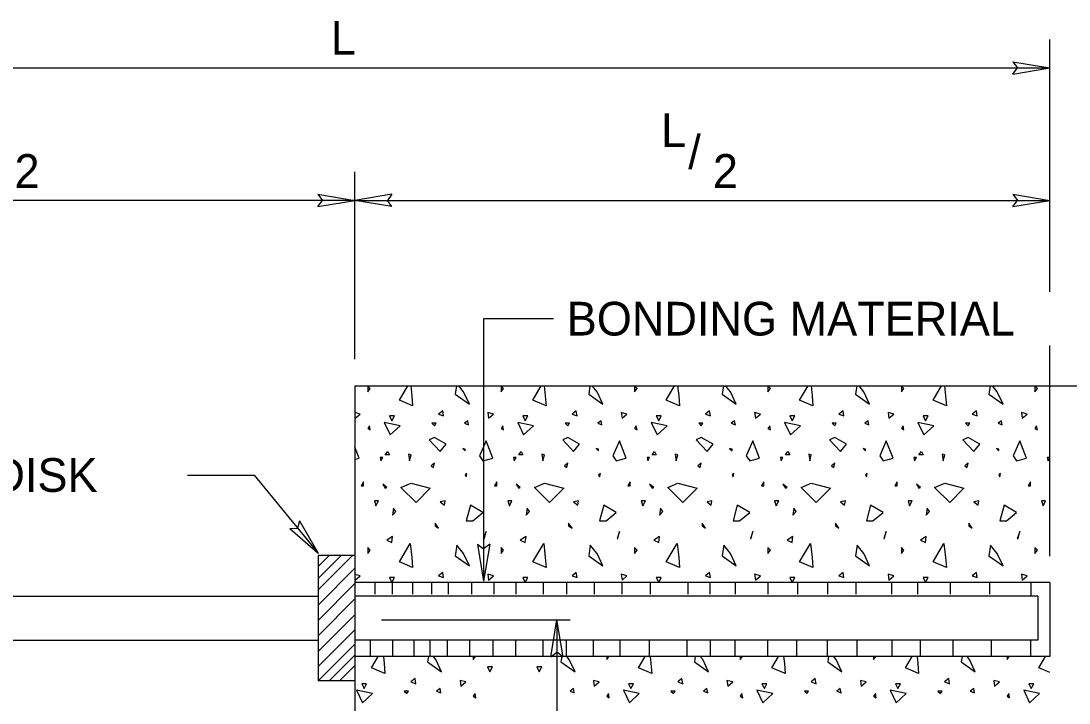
# Model space of a CAD drawing. Extents: x 2.92 to 10.05, y 1.3 to 10.63.
# Drawn here: x 5.007 to 6.873, y 6.811 to 8.026 of the extents above; entities that cross this region are included whole.
import ezdxf

# ---------------------------------------------------------------- set-up
doc = ezdxf.new("R2010")
doc.units = 0
for name, color, linetype in [('DETL-DIMS', 7, 'Continuous'), ('DETL-LINE', 7, 'Continuous'), ('DETL-NOTE', 7, 'Continuous'), ('DETL-PATT', 7, 'Continuous')]:
    doc.layers.add(name, color=color, linetype=linetype)

msp = doc.modelspace()

# ---------------------------------------------------------------- linework, layer by layer
at = {"layer": 'DETL-DIMS'}
for p, q in [((6.8384, 7.5436), (6.8384, 7.9925)), ((6.7725, 7.953), (6.8384, 7.942)), ((6.7725, 7.953), (6.7808, 7.942)), ((4.3073, 7.942), (6.8384, 7.942)), ((6.7725, 7.9311), (6.8384, 7.942)), ((6.7725, 7.9311), (6.7808, 7.942)), ((5.6014, 7.4233), (5.6014, 7.7572)), ((5.5355, 7.717), (5.6014, 7.706)), ((5.5355, 7.717), (5.5438, 7.706)), ((5.6673, 7.717), (5.6014, 7.706)), ((5.6673, 7.717), (5.6591, 7.706)), ((6.7725, 7.717), (6.8384, 7.706)), ((6.7725, 7.717), (6.7808, 7.706)), ((5.6014, 7.706), (4.3073, 7.706)), ((5.5355, 7.695), (5.6014, 7.706)), ((5.5355, 7.695), (5.5438, 7.706)), ((5.6673, 7.695), (5.6014, 7.706)), ((5.6014, 7.706), (6.8384, 7.706)), ((5.6673, 7.695), (5.6591, 7.706)), ((6.7725, 7.695), (6.8384, 7.706)), ((6.7725, 7.695), (6.7808, 7.706)), ((5.9549, 7.4956), (5.8305, 7.4956)), ((5.8305, 7.4956), (5.8305, 7.0282)), ((6.8384, 7.0728), (6.8384, 7.4481)), ((5.303, 7.2173), (5.4221, 7.2173)), ((5.4221, 7.2173), (5.5358, 7.0781)), ((5.5026, 7.136), (5.4993, 7.1227)), ((5.5026, 7.136), (5.5358, 7.0781)), ((5.4856, 7.1222), (5.4993, 7.1227)), ((5.4856, 7.1222), (5.5358, 7.0781)), ((5.8195, 7.0941), (5.8305, 7.0282)), ((5.8195, 7.0941), (5.8305, 7.0859)), ((5.8415, 7.0941), (5.8305, 7.0282)), ((5.8415, 7.0941), (5.8305, 7.0859)), ((5.6485, 6.9595), (5.9844, 6.9595)), ((5.9499, 6.8936), (5.9609, 6.9595)), ((5.9609, 6.9595), (5.9609, 6.5504)), ((5.9718, 6.8936), (5.9609, 6.9595)), ((5.9499, 6.8936), (5.9609, 6.9018)), ((5.9718, 6.8936), (5.9609, 6.9018))]:
    msp.add_line(p, q, dxfattribs=at)
at = {"layer": 'DETL-LINE'}
for p, q in [((5.6014, 7.3763), (7.8456, 7.3763)), ((5.6014, 7.3763), (5.6014, 6.549)), ((5.602, 7.0742), (5.5359, 7.0742)), ((5.5359, 7.0742), (5.5359, 6.8507)), ((6.8384, 7.0258), (5.6014, 7.0258)), ((5.6367, 7.0252), (5.6367, 7.0052)), ((5.6677, 7.0252), (5.6677, 7.0052)), ((5.7039, 7.0252), (5.7039, 7.0052)), ((5.7376, 7.0252), (5.7376, 7.0052)), ((5.7673, 7.0252), (5.7673, 7.0052)), ((5.8087, 7.0252), (5.8087, 7.0052)), ((5.8488, 7.0252), (5.8488, 7.0052)), ((5.8876, 7.0252), (5.8876, 7.0052)), ((5.9367, 7.0252), (5.9367, 7.0052)), ((5.9782, 7.0252), (5.9782, 7.0052)), ((6.0273, 7.0252), (6.0273, 7.0052)), ((6.0764, 7.0252), (6.0764, 7.0052)), ((6.1269, 7.0252), (6.1269, 7.0052)), ((6.1942, 7.0252), (6.1942, 7.0052)), ((6.2329, 7.0252), (6.2329, 7.0052)), ((6.2782, 7.0252), (6.2782, 7.0052)), ((6.3364, 7.0252), (6.3364, 7.0052)), ((6.3895, 7.0252), (6.3895, 7.0052)), ((6.4425, 7.0252), (6.4425, 7.0052)), ((6.4929, 7.0252), (6.4929, 7.0052)), ((6.5563, 7.0252), (6.5563, 7.0052)), ((6.6029, 7.0252), (6.6029, 7.0052)), ((6.6611, 7.0252), (6.6611, 7.0052)), ((6.7309, 7.0252), (6.7309, 7.0052)), ((6.8046, 7.0252), (6.8046, 7.0018)), ((6.8384, 7.0258), (6.8384, 6.8942)), ((4.3073, 7.0018), (5.5359, 7.0018)), ((6.8171, 7.0018), (5.6014, 7.0018)), ((6.8171, 7.0018), (6.8171, 6.9234)), ((4.3073, 6.9234), (5.5359, 6.9234)), ((6.8171, 6.9234), (5.6014, 6.9234)), ((5.6289, 6.8951), (5.6289, 6.9234)), ((5.669, 6.8951), (5.669, 6.9234)), ((5.7065, 6.8951), (5.7065, 6.9234)), ((5.735, 6.8951), (5.735, 6.9234)), ((5.766, 6.8951), (5.766, 6.9234)), ((5.8061, 6.8951), (5.8061, 6.9234)), ((5.8475, 6.8951), (5.8475, 6.9234)), ((5.8876, 6.8951), (5.8876, 6.9234)), ((5.9367, 6.8951), (5.9367, 6.9234)), ((5.9782, 6.8951), (5.9782, 6.9234)), ((6.026, 6.8951), (6.026, 6.9234)), ((6.0738, 6.8951), (6.0738, 6.9234)), ((6.1256, 6.8951), (6.1256, 6.9234)), ((6.1929, 6.8951), (6.1929, 6.9234)), ((6.2342, 6.8951), (6.2342, 6.9234)), ((6.2782, 6.8951), (6.2782, 6.9234)), ((6.3364, 6.8951), (6.3364, 6.9234)), ((6.3882, 6.8951), (6.3882, 6.9234)), ((6.4425, 6.8951), (6.4425, 6.9234)), ((6.4955, 6.8951), (6.4955, 6.9234)), ((6.5576, 6.8951), (6.5576, 6.9234)), ((6.608, 6.8951), (6.608, 6.9234)), ((6.6662, 6.8951), (6.6662, 6.9234)), ((6.7348, 6.8951), (6.7348, 6.9234)), ((6.8046, 6.8951), (6.8046, 6.9234)), ((6.8384, 6.8942), (5.6014, 6.8942)), ((5.602, 6.8507), (5.5359, 6.8507))]:
    msp.add_line(p, q, dxfattribs=at)
msp.add_lwpolyline([(6.2872, 6.8942), (6.2872, 6.8889), (6.2912, 6.8942)], dxfattribs=at)
at = {"layer": 'DETL-PATT'}
for p, q in [((5.5359, 7.0332), (5.5769, 7.0742)), ((5.5359, 7.0544), (5.5557, 7.0742)), ((5.5359, 7.0131), (5.5969, 7.0742)), ((5.5359, 6.9858), (5.6014, 7.0513)), ((5.5359, 6.9584), (5.6014, 7.024)), ((5.5359, 6.9311), (5.6014, 6.9967)), ((5.5359, 6.903), (5.6014, 6.9685)), ((5.5359, 6.8765), (5.6014, 6.942)), ((5.5359, 6.8508), (5.6014, 6.9164)), ((5.5553, 6.8507), (5.6014, 6.8968)), ((5.5738, 6.8507), (5.6014, 6.8783))]:
    msp.add_line(p, q, dxfattribs=at)
for points in [[(5.624, 7.3762), (5.624, 7.3656), (5.6285, 7.3716)], [(5.8615, 7.3762), (5.8615, 7.3656), (5.8661, 7.3716)], [(6.099, 7.3762), (6.099, 7.3656), (6.1036, 7.3716)], [(6.3365, 7.3762), (6.3365, 7.3656), (6.3411, 7.3716)], [(6.5741, 7.3762), (6.5741, 7.3656), (6.5787, 7.3716)], [(6.8116, 7.3762), (6.8116, 7.3656), (6.8162, 7.3716)], [(5.6628, 7.3226), (5.667, 7.3138), (5.6716, 7.3226)], [(5.7577, 7.3318), (5.7503, 7.3258), (5.7591, 7.3226)], [(5.8378, 7.3286), (5.8393, 7.3184), (5.8481, 7.3258)], [(5.9003, 7.3226), (5.9045, 7.3138), (5.9091, 7.3226)], [(5.9953, 7.3318), (5.9878, 7.3258), (5.9967, 7.3226)], [(6.0754, 7.3286), (6.0768, 7.3184), (6.0856, 7.3258)], [(6.1378, 7.3226), (6.1421, 7.3138), (6.1467, 7.3226)], [(6.2328, 7.3318), (6.2254, 7.3258), (6.2342, 7.3226)], [(6.3129, 7.3286), (6.3143, 7.3184), (6.3231, 7.3258)], [(6.3754, 7.3226), (6.3796, 7.3138), (6.3842, 7.3226)], [(6.4703, 7.3318), (6.4629, 7.3258), (6.4717, 7.3226)], [(6.5504, 7.3286), (6.5518, 7.3184), (6.5607, 7.3258)], [(6.6129, 7.3226), (6.6171, 7.3138), (6.6217, 7.3226)], [(6.7078, 7.3318), (6.7004, 7.3258), (6.7093, 7.3226)], [(6.788, 7.3286), (6.7894, 7.3184), (6.7982, 7.3258)], [(5.624, 7.3004), (5.6285, 7.2975), (5.6271, 7.3049)], [(5.6536, 7.3109), (5.6642, 7.2887), (5.6818, 7.3049)], [(5.7383, 7.3095), (5.7429, 7.3049), (5.7457, 7.3095)], [(5.7962, 7.3095), (5.8036, 7.3064), (5.8022, 7.3138)], [(5.8615, 7.3004), (5.8661, 7.2975), (5.8647, 7.3049)], [(5.8911, 7.3109), (5.9017, 7.2887), (5.9194, 7.3049)], [(5.9758, 7.3095), (5.9804, 7.3049), (5.9833, 7.3095)], [(6.0337, 7.3095), (6.0411, 7.3064), (6.0397, 7.3138)], [(6.099, 7.3004), (6.1036, 7.2975), (6.1022, 7.3049)], [(6.1287, 7.3109), (6.1393, 7.2887), (6.1569, 7.3049)], [(6.2134, 7.3095), (6.218, 7.3049), (6.2208, 7.3095)], [(6.2713, 7.3095), (6.2787, 7.3064), (6.2773, 7.3138)], [(6.3365, 7.3004), (6.3411, 7.2975), (6.3397, 7.3049)], [(6.3662, 7.3109), (6.3768, 7.2887), (6.3944, 7.3049)], [(6.4509, 7.3095), (6.4555, 7.3049), (6.4583, 7.3095)], [(6.5088, 7.3095), (6.5162, 7.3064), (6.5148, 7.3138)], [(6.5741, 7.3004), (6.5787, 7.2975), (6.5773, 7.3049)], [(6.6037, 7.3109), (6.6143, 7.2887), (6.632, 7.3049)], [(6.6884, 7.3095), (6.693, 7.3049), (6.6958, 7.3095)], [(6.7463, 7.3095), (6.7537, 7.3064), (6.7523, 7.3138)], [(6.8116, 7.3004), (6.8162, 7.2975), (6.8148, 7.3049)], [(5.7337, 7.2799), (5.7531, 7.2591), (5.7637, 7.2721), (5.7429, 7.2841)], [(5.829, 7.2425), (5.8467, 7.2471), (5.8347, 7.2781), (5.823, 7.2516)], [(5.9713, 7.2799), (5.9907, 7.2591), (6.0013, 7.2721), (5.9804, 7.2841)], [(6.0665, 7.2425), (6.0842, 7.2471), (6.0722, 7.2781), (6.0605, 7.2516)], [(6.2088, 7.2799), (6.2282, 7.2591), (6.2388, 7.2721), (6.218, 7.2841)], [(6.3041, 7.2425), (6.3217, 7.2471), (6.3097, 7.2781), (6.2981, 7.2516)], [(6.4463, 7.2799), (6.4657, 7.2591), (6.4763, 7.2721), (6.4555, 7.2841)], [(6.5416, 7.2425), (6.5593, 7.2471), (6.5473, 7.2781), (6.5356, 7.2516)], [(6.6838, 7.2799), (6.7033, 7.2591), (6.7138, 7.2721), (6.693, 7.2841)], [(6.7791, 7.2425), (6.7968, 7.2471), (6.7848, 7.2781), (6.7731, 7.2516)], [(5.6596, 7.2591), (5.6628, 7.2531), (5.6554, 7.2531)], [(5.7976, 7.2633), (5.7934, 7.2647), (5.7976, 7.2605)], [(5.8971, 7.2591), (5.9003, 7.2531), (5.8929, 7.2531)], [(6.0351, 7.2633), (6.0309, 7.2647), (6.0351, 7.2605)], [(6.1347, 7.2591), (6.1378, 7.2531), (6.1304, 7.2531)], [(6.2727, 7.2633), (6.2684, 7.2647), (6.2727, 7.2605)], [(6.3722, 7.2591), (6.3754, 7.2531), (6.368, 7.2531)], [(6.5102, 7.2633), (6.506, 7.2647), (6.5102, 7.2605)], [(6.6097, 7.2591), (6.6129, 7.2531), (6.6055, 7.2531)], [(6.7477, 7.2633), (6.7435, 7.2647), (6.7477, 7.2605)], [(5.6462, 7.2485), (5.6476, 7.2425), (5.6508, 7.2485)], [(5.6967, 7.2545), (5.6984, 7.2425), (5.7013, 7.2531)], [(5.8837, 7.2485), (5.8851, 7.2425), (5.8883, 7.2485)], [(5.9342, 7.2545), (5.936, 7.2425), (5.9388, 7.2531)], [(6.1213, 7.2485), (6.1227, 7.2425), (6.1258, 7.2485)], [(6.1717, 7.2545), (6.1735, 7.2425), (6.1763, 7.2531)], [(6.3588, 7.2485), (6.3602, 7.2425), (6.3634, 7.2485)], [(6.4093, 7.2545), (6.411, 7.2425), (6.4138, 7.2531)], [(6.5963, 7.2485), (6.5977, 7.2425), (6.6009, 7.2485)], [(6.6468, 7.2545), (6.6485, 7.2425), (6.6514, 7.2531)], [(5.7369, 7.2336), (5.7411, 7.2308), (5.7429, 7.2382)], [(5.9744, 7.2336), (5.9787, 7.2308), (5.9804, 7.2382)], [(6.212, 7.2336), (6.2162, 7.2308), (6.218, 7.2382)], [(6.4495, 7.2336), (6.4537, 7.2308), (6.4555, 7.2382)], [(6.687, 7.2336), (6.6913, 7.2308), (6.693, 7.2382)], [(5.6165, 7.2054), (5.6123, 7.198), (5.6165, 7.198)], [(5.7013, 7.2026), (5.7355, 7.1938), (5.7101, 7.1684), (5.6833, 7.1952)], [(5.8008, 7.2202), (5.7976, 7.2174), (5.7994, 7.2142)], [(5.8541, 7.2054), (5.8498, 7.198), (5.8541, 7.198)], [(5.9388, 7.2026), (5.973, 7.1938), (5.9476, 7.1684), (5.9208, 7.1952)], [(6.0383, 7.2202), (6.0351, 7.2174), (6.0369, 7.2142)], [(6.0916, 7.2054), (6.0874, 7.198), (6.0916, 7.198)], [(6.1763, 7.2026), (6.2105, 7.1938), (6.1851, 7.1684), (6.1583, 7.1952)], [(6.2758, 7.2202), (6.2727, 7.2174), (6.2744, 7.2142)], [(6.3291, 7.2054), (6.3249, 7.198), (6.3291, 7.198)], [(6.4138, 7.2026), (6.4481, 7.1938), (6.4227, 7.1684), (6.3958, 7.1952)], [(6.5134, 7.2202), (6.5102, 7.2174), (6.512, 7.2142)], [(6.5667, 7.2054), (6.5624, 7.198), (6.5667, 7.198)], [(6.6514, 7.2026), (6.6856, 7.1938), (6.6602, 7.1684), (6.6334, 7.1952)], [(6.7509, 7.2202), (6.7477, 7.2174), (6.7495, 7.2142)], [(6.8042, 7.2054), (6.8, 7.198), (6.8042, 7.198)], [(5.6554, 7.1938), (5.6582, 7.1952), (5.6508, 7.2012)], [(5.8929, 7.1938), (5.8957, 7.1952), (5.8883, 7.2012)], [(6.1304, 7.1938), (6.1333, 7.1952), (6.1258, 7.2012)], [(6.368, 7.1938), (6.3708, 7.1952), (6.3634, 7.2012)], [(6.6055, 7.1938), (6.6083, 7.1952), (6.6009, 7.2012)], [(5.636, 7.1712), (5.6388, 7.1624), (5.6434, 7.1712)], [(5.7531, 7.1698), (5.7605, 7.1638), (5.762, 7.1712)], [(5.8735, 7.1712), (5.8763, 7.1624), (5.8809, 7.1712)], [(5.9907, 7.1698), (5.9981, 7.1638), (5.9995, 7.1712)], [(6.111, 7.1712), (6.1138, 7.1624), (6.1184, 7.1712)], [(6.2282, 7.1698), (6.2356, 7.1638), (6.237, 7.1712)], [(6.3485, 7.1712), (6.3514, 7.1624), (6.356, 7.1712)], [(6.4657, 7.1698), (6.4731, 7.1638), (6.4745, 7.1712)], [(6.5861, 7.1712), (6.5889, 7.1624), (6.5935, 7.1712)], [(6.7033, 7.1698), (6.7107, 7.1638), (6.7121, 7.1712)], [(6.8236, 7.1712), (6.8264, 7.1624), (6.831, 7.1712)], [(5.6702, 7.1581), (5.6684, 7.1461), (5.6744, 7.1521)], [(5.811, 7.1355), (5.829, 7.1507), (5.8068, 7.1638), (5.7994, 7.1355)], [(5.9077, 7.1581), (5.906, 7.1461), (5.912, 7.1521)], [(6.0485, 7.1355), (6.0665, 7.1507), (6.0443, 7.1638), (6.0369, 7.1355)], [(6.1453, 7.1581), (6.1435, 7.1461), (6.1495, 7.1521)], [(6.2861, 7.1355), (6.3041, 7.1507), (6.2818, 7.1638), (6.2744, 7.1355)], [(6.3828, 7.1581), (6.381, 7.1461), (6.387, 7.1521)], [(6.5236, 7.1355), (6.5416, 7.1507), (6.5194, 7.1638), (6.512, 7.1355)], [(6.6203, 7.1581), (6.6185, 7.1461), (6.6245, 7.1521)], [(6.7611, 7.1355), (6.7791, 7.1507), (6.7569, 7.1638), (6.7495, 7.1355)], [(5.7443, 7.1313), (5.7443, 7.1267), (5.7503, 7.1225)], [(5.9818, 7.1313), (5.9818, 7.1267), (5.9878, 7.1225)], [(6.2194, 7.1313), (6.2194, 7.1267), (6.2254, 7.1225)], [(6.4569, 7.1313), (6.4569, 7.1267), (6.4629, 7.1225)], [(6.6944, 7.1313), (6.6944, 7.1267), (6.7004, 7.1225)], [(5.8304, 7.1045), (5.8318, 7.1045), (5.8347, 7.1165)], [(6.068, 7.1045), (6.0694, 7.1045), (6.0722, 7.1165)], [(6.3055, 7.1045), (6.3069, 7.1045), (6.3097, 7.1165)], [(6.543, 7.1045), (6.5444, 7.1045), (6.5473, 7.1165)], [(6.7805, 7.1045), (6.782, 7.1045), (6.7848, 7.1165)], [(5.6582, 7.1016), (5.667, 7.0971), (5.6684, 7.1076)], [(5.7027, 7.0702), (5.7041, 7.0526), (5.6804, 7.0628), (5.6998, 7.0956)], [(5.7828, 7.0925), (5.78, 7.0734), (5.805, 7.0554), (5.7948, 7.0776)], [(5.8957, 7.1016), (5.9045, 7.0971), (5.906, 7.1076)], [(5.9402, 7.0702), (5.9416, 7.0526), (5.918, 7.0628), (5.9374, 7.0956)], [(6.0203, 7.0925), (6.0175, 7.0734), (6.0425, 7.0554), (6.0323, 7.0776)], [(6.1333, 7.1016), (6.1421, 7.0971), (6.1435, 7.1076)], [(6.1777, 7.0702), (6.1791, 7.0526), (6.1555, 7.0628), (6.1749, 7.0956)], [(6.2578, 7.0925), (6.255, 7.0734), (6.2801, 7.0554), (6.2698, 7.0776)], [(6.3708, 7.1016), (6.3796, 7.0971), (6.381, 7.1076)], [(6.4153, 7.0702), (6.4167, 7.0526), (6.393, 7.0628), (6.4124, 7.0956)], [(6.4954, 7.0925), (6.4925, 7.0734), (6.5176, 7.0554), (6.5074, 7.0776)], [(6.6083, 7.1016), (6.6171, 7.0971), (6.6185, 7.1076)], [(6.6528, 7.0702), (6.6542, 7.0526), (6.6305, 7.0628), (6.65, 7.0956)], [(6.7329, 7.0925), (6.7301, 7.0734), (6.7551, 7.0554), (6.7449, 7.0776)], [(5.624, 7.0882), (5.624, 7.0776), (5.6285, 7.0836)], [(5.8615, 7.0882), (5.8615, 7.0776), (5.8661, 7.0836)], [(6.099, 7.0882), (6.099, 7.0776), (6.1036, 7.0836)], [(6.3365, 7.0882), (6.3365, 7.0776), (6.3411, 7.0836)], [(6.5741, 7.0882), (6.5741, 7.0776), (6.5787, 7.0836)], [(6.8116, 7.0882), (6.8116, 7.0776), (6.8162, 7.0836)], [(5.7577, 7.0438), (5.7503, 7.0378), (5.7591, 7.0346)], [(5.8378, 7.0406), (5.8393, 7.0304), (5.8481, 7.0378)], [(5.9953, 7.0438), (5.9878, 7.0378), (5.9967, 7.0346)], [(6.0754, 7.0406), (6.0768, 7.0304), (6.0856, 7.0378)], [(6.2328, 7.0438), (6.2254, 7.0378), (6.2342, 7.0346)], [(6.3129, 7.0406), (6.3143, 7.0304), (6.3231, 7.0378)], [(6.4703, 7.0438), (6.4629, 7.0378), (6.4717, 7.0346)], [(6.5504, 7.0406), (6.5518, 7.0304), (6.5607, 7.0378)], [(6.7078, 7.0438), (6.7004, 7.0378), (6.7093, 7.0346)], [(6.788, 7.0406), (6.7894, 7.0304), (6.7982, 7.0378)], [(5.8374, 6.8758), (5.8417, 6.8669), (5.8463, 6.8758)], [(5.9253, 6.8758), (5.9296, 6.8669), (5.9341, 6.8758)], [(5.7084, 6.855), (5.7009, 6.849), (5.7098, 6.8458)], [(5.7885, 6.8518), (5.7899, 6.8416), (5.7987, 6.849)], [(6.026, 6.8518), (6.0274, 6.8416), (6.0362, 6.849)], [(6.1834, 6.855), (6.176, 6.849), (6.1848, 6.8458)], [(6.2635, 6.8518), (6.2649, 6.8416), (6.2738, 6.849)], [(6.4209, 6.855), (6.4135, 6.849), (6.4224, 6.8458)], [(6.5011, 6.8518), (6.5025, 6.8416), (6.5113, 6.849)], [(6.6585, 6.855), (6.6511, 6.849), (6.6599, 6.8458)], [(6.7386, 6.8518), (6.74, 6.8416), (6.7488, 6.849)], [(5.6042, 6.8342), (5.6148, 6.812), (5.6325, 6.8282)], [(5.6134, 6.8458), (5.6176, 6.837), (5.6222, 6.8458)], [(5.6889, 6.8328), (5.6935, 6.8282), (5.6964, 6.8328)], [(5.7468, 6.8328), (5.7542, 6.8296), (5.7528, 6.837)], [(5.9844, 6.8328), (5.9918, 6.8296), (5.9904, 6.837)], [(6.0793, 6.8342), (6.0899, 6.812), (6.1075, 6.8282)], [(6.0885, 6.8458), (6.0927, 6.837), (6.0973, 6.8458)], [(6.164, 6.8328), (6.1686, 6.8282), (6.1714, 6.8328)], [(6.2219, 6.8328), (6.2293, 6.8296), (6.2279, 6.837)], [(6.3168, 6.8342), (6.3274, 6.812), (6.3451, 6.8282)], [(6.326, 6.8458), (6.3302, 6.837), (6.3348, 6.8458)], [(6.4015, 6.8328), (6.4061, 6.8282), (6.4089, 6.8328)], [(6.4594, 6.8328), (6.4668, 6.8296), (6.4654, 6.837)], [(6.5544, 6.8342), (6.5649, 6.812), (6.5826, 6.8282)], [(6.5635, 6.8458), (6.5678, 6.837), (6.5724, 6.8458)], [(6.6391, 6.8328), (6.6436, 6.8282), (6.6465, 6.8328)], [(6.6969, 6.8328), (6.7044, 6.8296), (6.7029, 6.837)], [(6.7919, 6.8342), (6.8025, 6.812), (6.8201, 6.8282)], [(6.8011, 6.8458), (6.8053, 6.837), (6.8099, 6.8458)], [(5.8121, 6.8236), (5.8167, 6.8208), (5.8153, 6.8282)], [(6.0496, 6.8236), (6.0542, 6.8208), (6.0528, 6.8282)], [(6.2872, 6.8236), (6.2918, 6.8208), (6.2904, 6.8282)], [(6.5247, 6.8236), (6.5293, 6.8208), (6.5279, 6.8282)], [(6.7622, 6.8236), (6.7668, 6.8208), (6.7654, 6.8282)]]:
    msp.add_lwpolyline(points, close=True, dxfattribs=at)
for points in [[(5.7007, 7.3763), (5.7027, 7.3582), (5.7041, 7.3406), (5.6804, 7.3508), (5.6955, 7.3763)], [(5.7822, 7.3763), (5.78, 7.3614), (5.805, 7.3434), (5.7948, 7.3656), (5.7862, 7.3763)], [(5.9382, 7.3763), (5.9402, 7.3582), (5.9416, 7.3406), (5.918, 7.3508), (5.933, 7.3763)], [(6.0197, 7.3763), (6.0175, 7.3614), (6.0425, 7.3434), (6.0323, 7.3656), (6.0237, 7.3763)], [(6.1757, 7.3763), (6.1777, 7.3582), (6.1791, 7.3406), (6.1555, 7.3508), (6.1705, 7.3763)], [(6.2572, 7.3763), (6.255, 7.3614), (6.2801, 7.3434), (6.2698, 7.3656), (6.2613, 7.3763)], [(6.4133, 7.3763), (6.4153, 7.3582), (6.4167, 7.3406), (6.393, 7.3508), (6.4081, 7.3763)], [(6.4947, 7.3763), (6.4925, 7.3614), (6.5176, 7.3434), (6.5074, 7.3656), (6.4988, 7.3763)], [(6.6508, 7.3763), (6.6528, 7.3582), (6.6542, 7.3406), (6.6305, 7.3508), (6.6456, 7.3763)], [(6.7323, 7.3763), (6.7301, 7.3614), (6.7551, 7.3434), (6.7449, 7.3656), (6.7363, 7.3763)], [(5.6014, 7.3206), (5.6017, 7.3184), (5.6105, 7.3258), (5.6014, 7.3283)], [(5.6014, 7.2451), (5.6091, 7.2471), (5.6014, 7.2671)], [(6.8377, 7.2485), (6.8338, 7.2485), (6.8353, 7.2425), (6.8377, 7.2471)], [(5.6014, 7.0326), (5.6017, 7.0304), (5.6105, 7.0378), (5.6014, 7.0403)], [(5.667, 7.0258), (5.6716, 7.0346), (5.6628, 7.0346), (5.667, 7.0258)], [(5.9045, 7.0258), (5.9091, 7.0346), (5.9003, 7.0346), (5.9045, 7.0258)], [(6.1421, 7.0258), (6.1467, 7.0346), (6.1378, 7.0346), (6.1421, 7.0258)], [(6.3796, 7.0258), (6.3842, 7.0346), (6.3754, 7.0346), (6.3796, 7.0258)], [(6.6171, 7.0258), (6.6217, 7.0346), (6.6129, 7.0346), (6.6171, 7.0258)], [(5.6519, 6.8942), (5.6533, 6.8815), (5.6547, 6.8638), (5.6311, 6.8741), (5.6429, 6.8942)], [(5.732, 6.8942), (5.7306, 6.8847), (5.7556, 6.8667), (5.7454, 6.8889), (5.7412, 6.8942)], [(5.8121, 6.8942), (5.8121, 6.8889), (5.8161, 6.8942)], [(5.9695, 6.8942), (5.9681, 6.8847), (5.9932, 6.8667), (5.9829, 6.8889), (5.9787, 6.8942)], [(6.0496, 6.8942), (6.0496, 6.8889), (6.0536, 6.8942)], [(6.1269, 6.8942), (6.1284, 6.8815), (6.1298, 6.8638), (6.1061, 6.8741), (6.118, 6.8942)], [(6.2071, 6.8942), (6.2056, 6.8847), (6.2307, 6.8667), (6.2205, 6.8889), (6.2162, 6.8942)], [(6.3645, 6.8942), (6.3659, 6.8815), (6.3673, 6.8638), (6.3436, 6.8741), (6.3555, 6.8942)], [(6.4446, 6.8942), (6.4432, 6.8847), (6.4682, 6.8667), (6.458, 6.8889), (6.4538, 6.8942)], [(6.5247, 6.8942), (6.5247, 6.8889), (6.5287, 6.8942)], [(6.602, 6.8942), (6.6034, 6.8815), (6.6048, 6.8638), (6.5812, 6.8741), (6.5931, 6.8942)], [(6.6821, 6.8942), (6.6807, 6.8847), (6.7058, 6.8667), (6.6955, 6.8889), (6.6913, 6.8942)], [(6.7622, 6.8942), (6.7622, 6.8889), (6.7662, 6.8942)], [(6.8384, 6.8655), (6.8187, 6.8741), (6.8306, 6.8942)]]:
    msp.add_lwpolyline(points, dxfattribs=at)

# ---------------------------------------------------------------- texts
at = {"layer": 'DETL-NOTE'}
for s, p in [('L', (5.5584, 7.9656)), ('L', (6.1464, 7.8012)), ('/', (6.1947, 7.7621)), ('2', (4.9953, 7.7285)), ('2', (6.2386, 7.7285)), ('BONDING MATERIAL', (5.9784, 7.4656)), ('RETENTION DISK', (4.47, 7.1873))]:
    msp.add_text(s, height=0.06, dxfattribs=at).set_placement(p)

doc.saveas('drawing.dxf')
